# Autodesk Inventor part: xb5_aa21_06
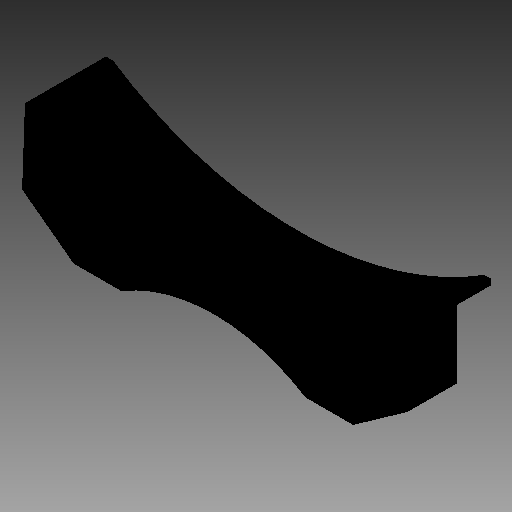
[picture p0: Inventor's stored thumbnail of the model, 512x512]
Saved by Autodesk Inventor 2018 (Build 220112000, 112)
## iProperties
Company: TraceParts S.A.
Created: 2018-05
Part Number: xb5_aa21_06
Checked By: TraceParts S.A.
Material: Generic
Catalog Web Link: www.traceparts.com
Document SubType Name: Modeling
Designer: TraceParts
Density: 1 g/cm^3
Appearance: Default
Author: TraceParts
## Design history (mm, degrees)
feature "xb5_aa21_06.ipt"
body "Solid1"
